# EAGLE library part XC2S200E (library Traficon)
Xilinx FPGA Spartan II XC2S200 PQFP 208 Created by Colin O'Flynn [coflynn@newae.com] This part has been used extensively in real life, and should be correct!
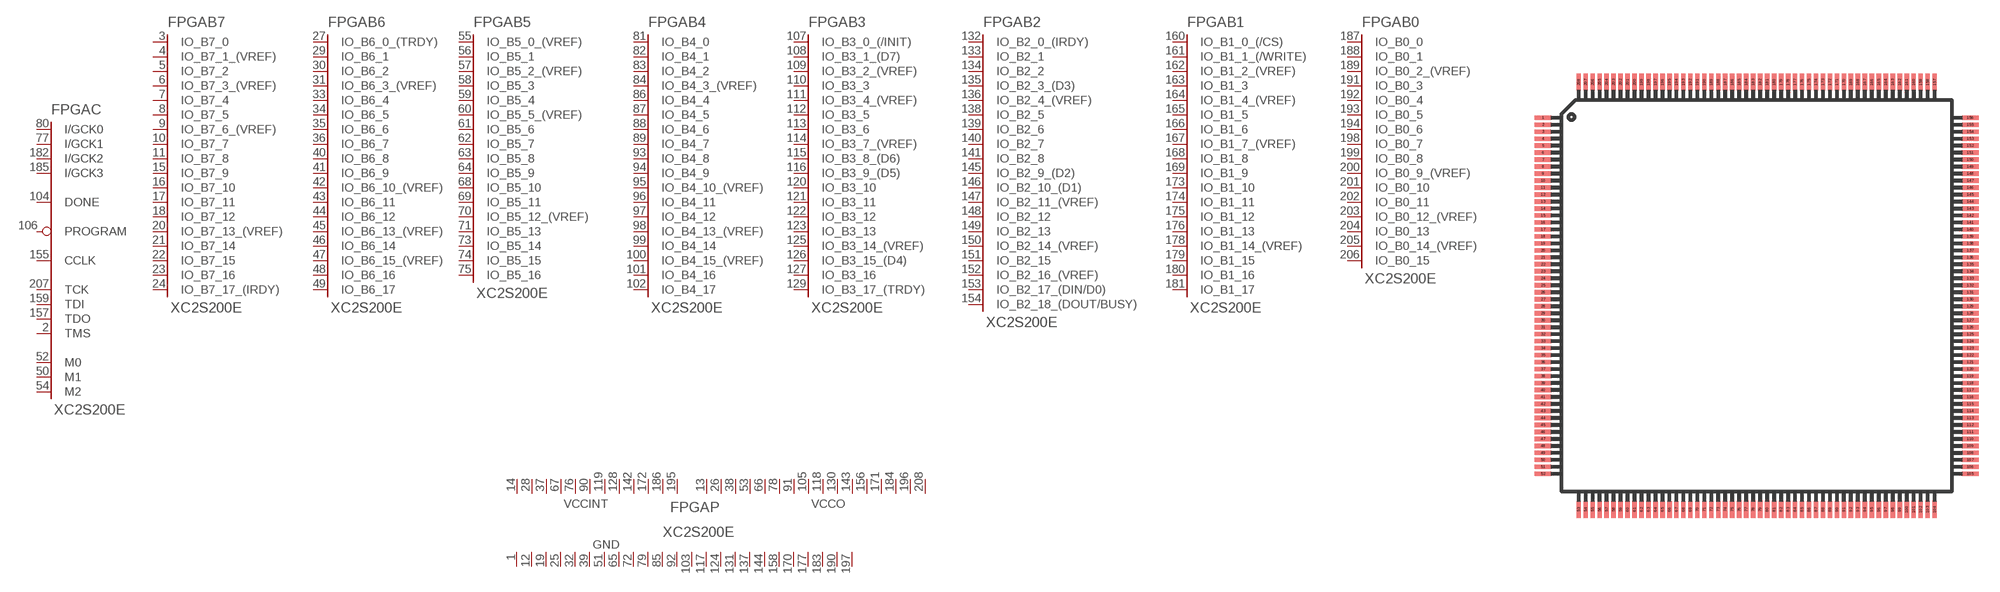
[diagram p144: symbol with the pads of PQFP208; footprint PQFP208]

Designator prefix FPGA; gates P=PWR_XC2S200 B7=XC2S_B7 B6=XC2S_B6 B4=XC2S_B4 B3=XC2S_B3 B2=XC2S_B2 B1=XC2S_B1 B0=XC2S_B0 B5=XC2S_B5 C=XC2S_C

## XC2S200E-PQ208  [PQFP208]
1  P:GND  pwr
2  C:TMS
3  B7:IO_B7_0
4  B7:IO_B7_1_(VREF)
5  B7:IO_B7_2
6  B7:IO_B7_3_(VREF)
7  B7:IO_B7_4
8  B7:IO_B7_5
9  B7:IO_B7_6_(VREF)
10  B7:IO_B7_7
11  B7:IO_B7_8
12  P:GND  pwr
13  P:VCCO  pwr
14  P:VCCINT  pwr
15  B7:IO_B7_9
16  B7:IO_B7_10
17  B7:IO_B7_11
18  B7:IO_B7_12
19  P:GND  pwr
20  B7:IO_B7_13_(VREF)
21  B7:IO_B7_14
22  B7:IO_B7_15
23  B7:IO_B7_16
24  B7:IO_B7_17_(IRDY)
25  P:GND  pwr
26  P:VCCO  pwr
27  B6:IO_B6_0_(TRDY)
28  P:VCCINT  pwr
29  B6:IO_B6_1
30  B6:IO_B6_2
31  B6:IO_B6_3_(VREF)
32  P:GND  pwr
33  B6:IO_B6_4
34  B6:IO_B6_5
35  B6:IO_B6_6
36  B6:IO_B6_7
37  P:VCCINT  pwr
38  P:VCCO  pwr
39  P:GND  pwr
40  B6:IO_B6_8
41  B6:IO_B6_9
42  B6:IO_B6_10_(VREF)
43  B6:IO_B6_11
44  B6:IO_B6_12
45  B6:IO_B6_13_(VREF)
46  B6:IO_B6_14
47  B6:IO_B6_15_(VREF)
48  B6:IO_B6_16
49  B6:IO_B6_17
50  C:M1  in
51  P:GND  pwr
52  C:M0  in
53  P:VCCO  pwr
54  C:M2  in
55  B5:IO_B5_0_(VREF)
56  B5:IO_B5_1
57  B5:IO_B5_2_(VREF)
58  B5:IO_B5_3
59  B5:IO_B5_4
60  B5:IO_B5_5_(VREF)
61  B5:IO_B5_6
62  B5:IO_B5_7
63  B5:IO_B5_8
64  B5:IO_B5_9
65  P:GND  pwr
66  P:VCCO  pwr
67  P:VCCINT  pwr
68  B5:IO_B5_10
69  B5:IO_B5_11
70  B5:IO_B5_12_(VREF)
71  B5:IO_B5_13
72  P:GND  pwr
73  B5:IO_B5_14
74  B5:IO_B5_15
75  B5:IO_B5_16
76  P:VCCINT  pwr
77  C:I/GCK1
78  P:VCCO  pwr
79  P:GND  pwr
80  C:I/GCK0
81  B4:IO_B4_0
82  B4:IO_B4_1
83  B4:IO_B4_2
84  B4:IO_B4_3_(VREF)
85  P:GND  pwr
86  B4:IO_B4_4
87  B4:IO_B4_5
88  B4:IO_B4_6
89  B4:IO_B4_7
90  P:VCCINT  pwr
91  P:VCCO  pwr
92  P:GND  pwr
93  B4:IO_B4_8
94  B4:IO_B4_9
95  B4:IO_B4_10_(VREF)
96  B4:IO_B4_11
97  B4:IO_B4_12
98  B4:IO_B4_13_(VREF)
99  B4:IO_B4_14
100  B4:IO_B4_15_(VREF)
101  B4:IO_B4_16
102  B4:IO_B4_17
103  P:GND  pwr
104  C:DONE
105  P:VCCO  pwr
106  C:PROGRAM
107  B3:IO_B3_0_(/INIT)
108  B3:IO_B3_1_(D7)
109  B3:IO_B3_2_(VREF)
110  B3:IO_B3_3
111  B3:IO_B3_4_(VREF)
112  B3:IO_B3_5
113  B3:IO_B3_6
114  B3:IO_B3_7_(VREF)
115  B3:IO_B3_8_(D6)
116  B3:IO_B3_9_(D5)
117  P:GND  pwr
118  P:VCCO  pwr
119  P:VCCINT  pwr
120  B3:IO_B3_10
121  B3:IO_B3_11
122  B3:IO_B3_12
123  B3:IO_B3_13
124  P:GND  pwr
125  B3:IO_B3_14_(VREF)
126  B3:IO_B3_15_(D4)
127  B3:IO_B3_16
128  P:VCCINT  pwr
129  B3:IO_B3_17_(TRDY)
130  P:VCCO  pwr
131  P:GND  pwr
132  B2:IO_B2_0_(IRDY)
133  B2:IO_B2_1
134  B2:IO_B2_2
135  B2:IO_B2_3_(D3)
136  B2:IO_B2_4_(VREF)
137  P:GND  pwr
138  B2:IO_B2_5
139  B2:IO_B2_6
140  B2:IO_B2_7
141  B2:IO_B2_8
142  P:VCCINT  pwr
143  P:VCCO  pwr
144  P:GND  pwr
145  B2:IO_B2_9_(D2)
146  B2:IO_B2_10_(D1)
147  B2:IO_B2_11_(VREF)
148  B2:IO_B2_12
149  B2:IO_B2_13
150  B2:IO_B2_14_(VREF)
151  B2:IO_B2_15
152  B2:IO_B2_16_(VREF)
153  B2:IO_B2_17_(DIN/D0)
154  B2:IO_B2_18_(DOUT/BUSY)
155  C:CCLK
156  P:VCCO  pwr
157  C:TDO
158  P:GND  pwr
159  C:TDI
160  B1:IO_B1_0_(/CS)
161  B1:IO_B1_1_(/WRITE)
162  B1:IO_B1_2_(VREF)
163  B1:IO_B1_3
164  B1:IO_B1_4_(VREF)
165  B1:IO_B1_5
166  B1:IO_B1_6
167  B1:IO_B1_7_(VREF)
168  B1:IO_B1_8
169  B1:IO_B1_9
170  P:GND  pwr
171  P:VCCO  pwr
172  P:VCCINT  pwr
173  B1:IO_B1_10
174  B1:IO_B1_11
175  B1:IO_B1_12
176  B1:IO_B1_13
177  P:GND  pwr
178  B1:IO_B1_14_(VREF)
179  B1:IO_B1_15
180  B1:IO_B1_16
181  B1:IO_B1_17
182  C:I/GCK2
183  P:GND  pwr
184  P:VCCO  pwr
185  C:I/GCK3
186  P:VCCINT  pwr
187  B0:IO_B0_0
188  B0:IO_B0_1
189  B0:IO_B0_2_(VREF)
190  P:GND  pwr
191  B0:IO_B0_3
192  B0:IO_B0_4
193  B0:IO_B0_5
194  B0:IO_B0_6
195  P:VCCINT  pwr
196  P:VCCO  pwr
197  P:GND  pwr
198  B0:IO_B0_7
199  B0:IO_B0_8
200  B0:IO_B0_9_(VREF)
201  B0:IO_B0_10
202  B0:IO_B0_11
203  B0:IO_B0_12_(VREF)
204  B0:IO_B0_13
205  B0:IO_B0_14_(VREF)
206  B0:IO_B0_15
207  C:TCK
208  P:VCCO  pwr

## Footprint PQFP208 (pad centres in mm)
PLASTIC QUAD FLAT PACK
smd 1.2 x 0.32: 1 -15.3,12.75; 2 -15.3,12.25; 3 -15.3,11.75; 4 -15.3,11.25; 5 -15.3,10.75; 6 -15.3,10.25; 7 -15.3,9.75; 8 -15.3,9.25; 9 -15.3,8.75; 10 -15.3,8.25; 11 -15.3,7.75; 12 -15.3,7.25; 13 -15.3,6.75; 14 -15.3,6.25; 15 -15.3,5.75; 16 -15.3,5.25; 17 -15.3,4.75; 18 -15.3,4.25; 19 -15.3,3.75; 20 -15.3,3.25; 21 -15.3,2.75; 22 -15.3,2.25; 23 -15.3,1.75; 24 -15.3,1.25; 25 -15.3,0.75; 26 -15.3,0.25; 27 -15.3,-0.25; 28 -15.3,-0.75; 29 -15.3,-1.25; 30 -15.3,-1.75; 31 -15.3,-2.25; 32 -15.3,-2.75; 33 -15.3,-3.25; 34 -15.3,-3.75; 35 -15.3,-4.25; 36 -15.3,-4.75; 37 -15.3,-5.25; 38 -15.3,-5.75; 39 -15.3,-6.25; 40 -15.3,-6.75; 41 -15.3,-7.25; 42 -15.3,-7.75; 43 -15.3,-8.25; 44 -15.3,-8.75; 45 -15.3,-9.25; 46 -15.3,-9.75; 47 -15.3,-10.25; 48 -15.3,-10.75; 49 -15.3,-11.25; 50 -15.3,-11.75; 51 -15.3,-12.25; 52 -15.3,-12.75; 105 15.3,-12.75; 106 15.3,-12.25; 107 15.3,-11.75; 108 15.3,-11.25; 109 15.3,-10.75; 110 15.3,-10.25; 111 15.3,-9.75; 112 15.3,-9.25; 113 15.3,-8.75; 114 15.3,-8.25; 115 15.3,-7.75; 116 15.3,-7.25; 117 15.3,-6.75; 118 15.3,-6.25; 119 15.3,-5.75; 120 15.3,-5.25; 121 15.3,-4.75; 122 15.3,-4.25; 123 15.3,-3.75; 124 15.3,-3.25; 125 15.3,-2.75; 126 15.3,-2.25; 127 15.3,-1.75; 128 15.3,-1.25; 129 15.3,-0.75; 130 15.3,-0.25; 131 15.3,0.25; 132 15.3,0.75; 133 15.3,1.25; 134 15.3,1.75; 135 15.3,2.25; 136 15.3,2.75; 137 15.3,3.25; 138 15.3,3.75; 139 15.3,4.25; 140 15.3,4.75; 141 15.3,5.25; 142 15.3,5.75; 143 15.3,6.25; 144 15.3,6.75; 145 15.3,7.25; 146 15.3,7.75; 147 15.3,8.25; 148 15.3,8.75; 149 15.3,9.25; 150 15.3,9.75; 151 15.3,10.25; 152 15.3,10.75; 153 15.3,11.25; 154 15.3,11.75; 155 15.3,12.25; 156 15.3,12.75
smd 0.32 x 1.2: 53 -12.75,-15.3; 54 -12.25,-15.3; 55 -11.75,-15.3; 56 -11.25,-15.3; 57 -10.75,-15.3; 58 -10.25,-15.3; 59 -9.75,-15.3; 60 -9.25,-15.3; 61 -8.75,-15.3; 62 -8.25,-15.3; 63 -7.75,-15.3; 64 -7.25,-15.3; 65 -6.75,-15.3; 66 -6.25,-15.3; 67 -5.75,-15.3; 68 -5.25,-15.3; 69 -4.75,-15.3; 70 -4.25,-15.3; 71 -3.75,-15.3; 72 -3.25,-15.3; 73 -2.75,-15.3; 74 -2.25,-15.3; 75 -1.75,-15.3; 76 -1.25,-15.3; 77 -0.75,-15.3; 78 -0.25,-15.3; 79 0.25,-15.3; 80 0.75,-15.3; 81 1.25,-15.3; 82 1.75,-15.3; 83 2.25,-15.3; 84 2.75,-15.3; 85 3.25,-15.3; 86 3.75,-15.3; 87 4.25,-15.3; 88 4.75,-15.3; 89 5.25,-15.3; 90 5.75,-15.3; 91 6.25,-15.3; 92 6.75,-15.3; 93 7.25,-15.3; 94 7.75,-15.3; 95 8.25,-15.3; 96 8.75,-15.3; 97 9.25,-15.3; 98 9.75,-15.3; 99 10.25,-15.3; 100 10.75,-15.3; 101 11.25,-15.3; 102 11.75,-15.3; 103 12.25,-15.3; 104 12.75,-15.3; 157 12.75,15.3; 158 12.25,15.3; 159 11.75,15.3; 160 11.25,15.3; 161 10.75,15.3; 162 10.25,15.3; 163 9.75,15.3; 164 9.25,15.3; 165 8.75,15.3; 166 8.25,15.3; 167 7.75,15.3; 168 7.25,15.3; 169 6.75,15.3; 170 6.25,15.3; 171 5.75,15.3; 172 5.25,15.3; 173 4.75,15.3; 174 4.25,15.3; 175 3.75,15.3; 176 3.25,15.3; 177 2.75,15.3; 178 2.25,15.3; 179 1.75,15.3; 180 1.25,15.3; 181 0.75,15.3; 182 0.25,15.3; 183 -0.25,15.3; 184 -0.75,15.3; 185 -1.25,15.3; 186 -1.75,15.3; 187 -2.25,15.3; 188 -2.75,15.3; 189 -3.25,15.3; 190 -3.75,15.3; 191 -4.25,15.3; 192 -4.75,15.3; 193 -5.25,15.3; 194 -5.75,15.3; 195 -6.25,15.3; 196 -6.75,15.3; 197 -7.25,15.3; 198 -7.75,15.3; 199 -8.25,15.3; 200 -8.75,15.3; 201 -9.25,15.3; 202 -9.75,15.3; 203 -10.25,15.3; 204 -10.75,15.3; 205 -11.25,15.3; 206 -11.75,15.3; 207 -12.25,15.3; 208 -12.75,15.3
